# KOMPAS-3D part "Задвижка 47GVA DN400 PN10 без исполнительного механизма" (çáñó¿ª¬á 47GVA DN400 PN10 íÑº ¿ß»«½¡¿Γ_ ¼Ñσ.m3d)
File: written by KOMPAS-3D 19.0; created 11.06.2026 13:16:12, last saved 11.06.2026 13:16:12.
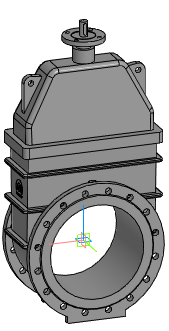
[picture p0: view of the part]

Document properties: Автор: Евгений; Полное имя файла: Z:\3.Личные\kachalov\001_3d для проектировщиков\2.2 Тип 47GVA, 47GVA.Z\_stp\_stp_Задвижка 47GVA DN40-DN1000 без исп.мех\Задвижка 47GVA DN400 PN10 без исполнит_ мех.m3d

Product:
- Part/product: Задвижка 47GVA DN400 PN10 без исполнительного механизма

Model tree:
1. Операция без истории:1  (labels: Задвижка 47GVA DN400 PN10 без исполнительного механизма)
